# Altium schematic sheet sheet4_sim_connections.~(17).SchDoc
size A3; Author: Mauri Shadi; CompanyName: BFH; DrawnBy: Mauri Shadi; SheetNumber: 1; SheetTotal: 2
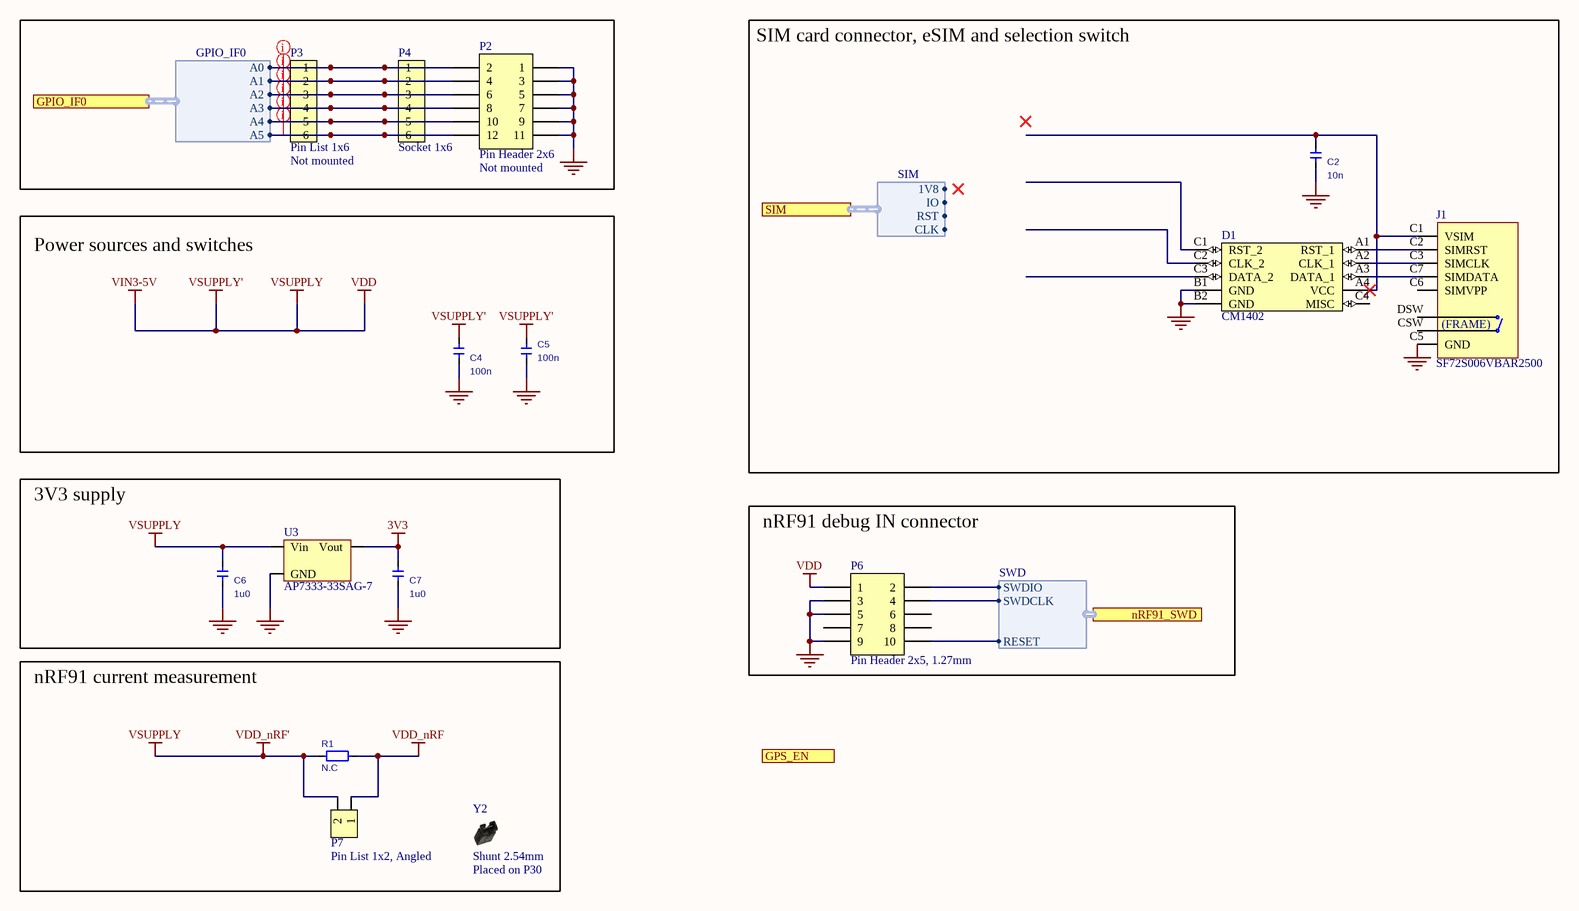
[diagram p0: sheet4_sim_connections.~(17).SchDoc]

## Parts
C2  10n  [0603(1608)C]
C4  100n  [0603(1608)C]
C5  100n  [0603(1608)C]
C6  1u0  [0603(1608)C]
C7  1u0  [0603(1608)C]
D1  CM1402  [CM1402]
J1  SF72S006VBAR2500  [SF72S006VBAR2500]
P2  Pin Header 2x6  Assembly: Not mounted  [HDR_2x6-NC]
P3  Pin List 1x6  Assembly: Not mounted  [LIST_1x6_SMD-NC]
P4  Socket 1x6  [SOCKET_1x6_SMD]
P6  Pin Header 2x5, 1.27mm  [HDR_2x5-SMD-1.27mm-K]
P7  Pin List 1x2, Angled  [LIST_ANG_1x2-SMD-2.54MM]
R1  N.C  [0603(1608)]
U3  AP7333-33SAG-7  [SOT-23A]
Y2  Shunt 2.54mm  Assembly: Placed on P30  [Shunt_2.54mm_Horizontal]

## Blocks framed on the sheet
SIM card connector, eSIM and selection switch: C2 D1 J1
Power sources and switches: C4 C5
3V3 supply: C6 C7 U3
nRF91 debug IN connector: P6
nRF91 current measurement: P7 R1 Y2

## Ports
GPIO_IF0 (harness GPIO_IF0, see sheet2_nRF9160[7C]), GPS_EN (out, see sheet2_nRF9160[7C]), nRF91_SWD (harness SWD, see sheet2_nRF9160[7C]), SIM (harness SIM, see sheet2_nRF9160[7D])

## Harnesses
SWD: SWDIO, SWDCLK, RESET
GPIO_IF0: A0, A1, A2, A3, A4, A5
SIM: CLK, IO, 1V8, RST

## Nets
3V3: C7.1 U3.2(Vout)
GND: C2.2 C4.2 C5.1 C6.2 C7.2 D1.B1(GND) D1.B2(GND) J1.0(GND) J1.C5(GND) P2.1 P2.3 P2.5 P2.7 P2.9 P2.11 P6.3 P6.5 P6.9 U3.3(GND)
VDD: C4.1 C5.2 C6.1 P6.1 P7.2 R1.2 U3.1(Vin)  [also labelled VDD_nRF', VIN3-5V, VSUPPLY, VSUPPLY']
VDD_nRF: P7.1 R1.1
NetC2_1: C2.1 D1.A4(VCC) J1.C1(VSIM)
NetD1_A1: D1.A1(RST_1) J1.C2(SIMRST)
NetD1_A2: D1.A2(CLK_1) J1.C3(SIMCLK)
NetD1_A3: D1.A3(DATA_1) J1.C7(SIMDATA)
NetP2_2: P2.2 P3.1 P4.1 ; port GPIO_IF0.A0
NetP2_4: P2.4 P3.2 P4.2 ; port GPIO_IF0.A1
NetP2_6: P2.6 P3.3 P4.3 ; port GPIO_IF0.A2
NetP2_8: P2.8 P3.4 P4.4 ; port GPIO_IF0.A3
NetP2_10: P2.10 P3.5 P4.5 ; port GPIO_IF0.A4
NetP2_12: P2.12 P3.6 P4.6 ; port GPIO_IF0.A5
NetP6_2: P6.2 ; port nRF91_SWD.SWDIO
NetP6_4: P6.4 ; port nRF91_SWD.SWDCLK
NetP6_10: P6.10 ; port nRF91_SWD.RESET

Not connected (* = marked no-connect by the designer): D1 C1(RST_2) C2(CLK_2) C3(DATA_2) C4(MISC); J1 C6(SIMVPP) CSW DSW; P6 6 7 8

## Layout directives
net class GPIO: NetP2_2, NetP2_4, NetP2_6, NetP2_8, NetP2_10, NetP2_12

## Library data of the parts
C2 = C0603_4_10n_25V: Cer Chip Capacitor / 10n/ +-5%/ 25V; Manufacturer Part Number: C0603C103M3RACTU; Manufacturer 1: KEMET; Special Value 1: +-5%; Dielectric Material: Ceramic; Capacitance: 10nF; Tolerance: 20%; Dielectric: X7R; Dissipation Factor: 3.5%
C4 C5 = C0603_5_100n_25V: Cer Chip Capacitor / 100n/ +-5%/ 25V; Manufacturer Part Number: CC0603KRX7R8BB104; Manufacturer 1: Yageo; Special Value 1: +-5%; Capacitance: 100nF; Tolerance: 10%; Dielectric: X7R
C6 C7 = C0603_6_1u0_25V: Cer Chip Capacitor / 1u0 / +-10%/ 25V; Manufacturer Part Number: CL10B105KA8VPNC; Manufacturer 1: Samsung; Special Value 1: +-10%; Capacitance: 1uF; Tolerance: 10%
D1 = CM1402: EMI Network Filter Arrays SIM CARD EMI FILTER WITH ESD PROTECTION; Manufacturer: ON Semiconductor; Manufacturer Part Number: CM1402-03CP; Part number IPS: 00000009949; Note: N.A.; Pad Count: 10
J1 = SF72S006VBAR2500: n 8 (6 + 2) Position Card Connector NANO SIM Surface Mount, Right Angle Gold; Manufacturer: JAE Electronics; Part number IPS: 00000009956; Note: N.A.; Pad Count: 8
P2 = Pin Header 2x6, N.C.: Pin Header 2x6, 2.54mm (100mil); Manufacturer: N.A.; Pad Count: 12
P3 = Pin List 1x6 SMD, N.C.: Pin List 1x6, 2.54mm (100mil), SMD; Manufacturer: W-CON; Manufacturer Part Number: 1125-1106S0M116R2; Note: N.A.; Artikkelnr Noca: 55010026; Pad Count: 6
P4 = Socket 1x6 SMD: Socket 1x6, 2.54mm (100mil), SMD; Manufacturer: W-CON; Manufacturer Part Number: 2171-106MS0CUNR1; Part number IPS: 00000009964; Note: N.A.; Artikkelnr Noca: 55030001; Pad Count: 6
P6 = Pin Header 2x5 SMD, 1.27mm, KS: Pin Header 2x5, 1.27mm (50mil), SMD, Keying Shroud; Manufacturer: W-CON; Manufacturer Part Number: 3132-10MS0BK00R1; Part number IPS: 00000009968; Note: N.A.; Artikkelnr Noca: 55010009; Pad Count: 10
P7 = Pin List Ang 1x2 SMD, 2.54mm: Pin List 1x2, 2.54mm (100mil), Right Angled, SMD; Manufacturer: W-CON; Manufacturer Part Number: 1125B-1102S0Z135R2; Part number IPS: 00000009972; Note: N.A.; Artikkelnr Noca: 55010023; Pad Count: 2
R1 = R0603_0_0E: Chip Resistor / 0E / 1% / 50V / 100mW / 0603(1608); Manufacturer Part Number: ERJ-3GEY0R00V; Manufacturer 1: Panasonic; Resistance: 0mR; Voltage Rating: 75V; Tolerance: 0%; Temperature Coefficient: 600ppm/°C
U3 = AP7333-33SAG-7: 300mA, Low Quiescent Current, Fast Transient Low Dropout Linear Regulator; Manufacturer: Diodes Incorporated; Part number IPS: 00000001673; Note: N.A.; Artikkelnr Noca: 17039216; Pad Count: 3
Y2 = SHUNT JUMPER 2.54mm BLACK GOLD Horizontal (Obsolete): Shunt Jumper 2.54mm Black; Manufacturer: N.A.; Part number IPS: 00000001916; Note: SHUNT JUMPER .1" BLACK GOLD, h=6.00mm, w=5.00mm; Artikkelnr Noca: 56099001; Pad Count: 2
